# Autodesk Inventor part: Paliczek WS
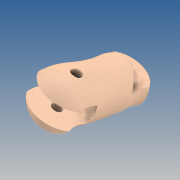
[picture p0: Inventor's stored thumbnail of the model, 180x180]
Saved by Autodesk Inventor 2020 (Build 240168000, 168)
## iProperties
Created: 2019-10
Part Number: Paliczek WS
Material: GFRP
Document SubType Name: Modeling
Designer: yello
Density: 1.75 g/cm^3
Appearance: Default
Author: yello
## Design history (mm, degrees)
feature "Paliczek WS"
sketch "Sketch1"
  geometry: C1 r 2 at (0, 0); 1 further point
  constraints: 1 centre point
  dimensions: "d0" = 4 diameter of C1
extrude "Extrusion1" cut sketch "Sketch1" stored distance "d1" = 100; taper "d2" = 0 deg
sketch "Sketch2"
  geometry: C1 r 5 at (0, 0); 1 further point
  constraints: 1 centre point
  dimensions: "d3" = 10 diameter of C1
extrude "Extrusion2" cut sketch "Sketch2" distance "d4" = 8; taper "d5" = 0 deg
body "Solid1"
